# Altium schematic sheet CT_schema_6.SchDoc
size 226 x 144 mm
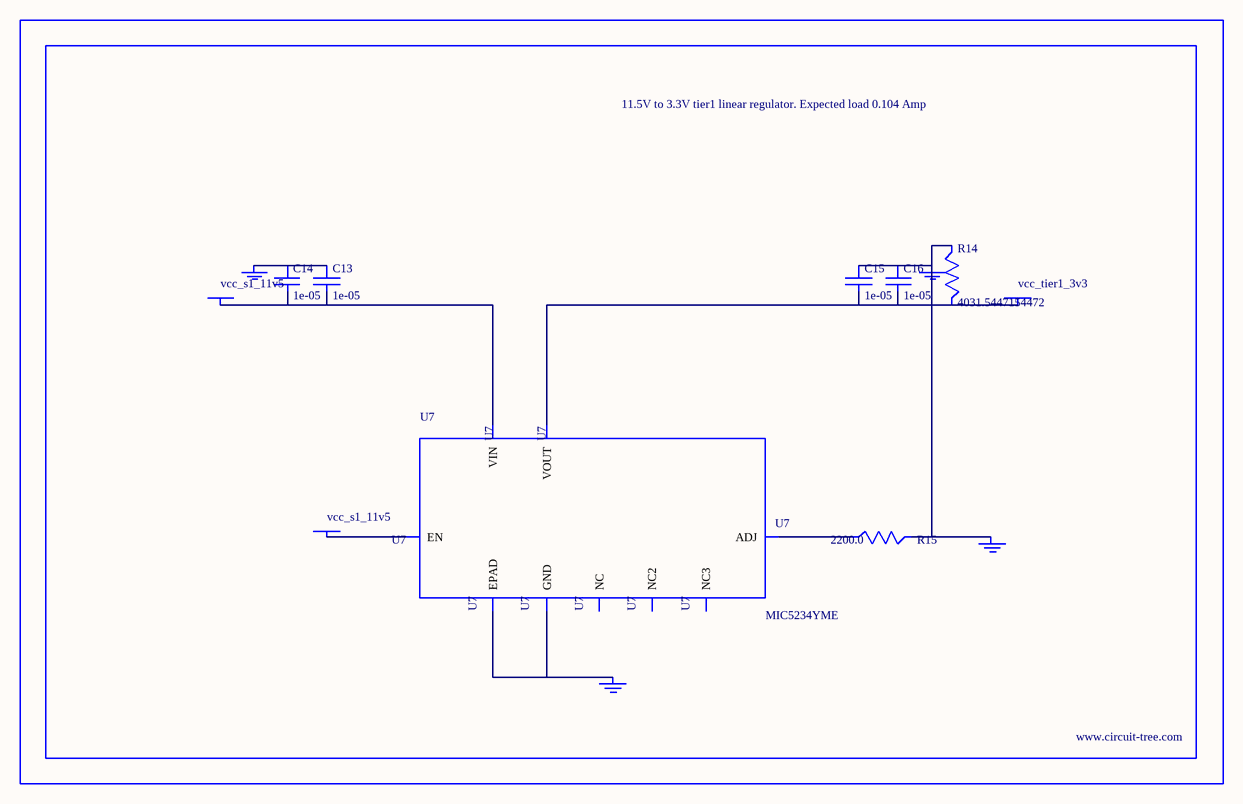
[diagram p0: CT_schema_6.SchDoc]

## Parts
BORDER5  (no value)
C13  1e-05  [C1210]
C14  1e-05  [C1210]
C15  1e-05  [C1210]
C16  1e-05  [C1210]
GND_INSTANCE_5_0  (no value)
GND_INSTANCE_5_1  (no value)
GND_INSTANCE_5_2  (no value)
GND_INSTANCE_5_3  (no value)
POWER_INSTANCE_5_0  vcc_tier1_3v3
POWER_INSTANCE_5_1  vcc_s1_11v5
POWER_INSTANCE_5_2  vcc_s1_11v5
R14  4031.5447154472  [R0603]
R15  2200.0  [R0603]
U7  MIC5234YME  [SOIC-8_EP]

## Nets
NetC13_1: C13.1 C14.1 GND_INSTANCE_5_3.0(GND)
NetC13_2: C13.2 C14.2 POWER_INSTANCE_5_2.0(PWR) U7.8(VIN)
NetC15_1: C15.1 C16.1 GND_INSTANCE_5_0.0(GND) GND_INSTANCE_5_1.0(GND) R14.1 R15.2
NetC15_2: C15.2 C16.2 POWER_INSTANCE_5_0.0(PWR) R14.2 U7.1(VOUT)
NetGND_INSTANCE_5_2_0: GND_INSTANCE_5_2.0(GND) U7.7(GND) U7.EPAD
NetPOWER_INSTANCE_5_1_0: POWER_INSTANCE_5_1.0(PWR) U7.5(EN)
NetR15_1: R15.1 U7.4(ADJ)

Not connected (* = marked no-connect by the designer): U7 2(NC) 3(NC2) 6(NC3)

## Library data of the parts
BORDER5 = BORDER_PAGE5
C13-C16 = C1210C106K5PACTU
GND_INSTANCE_5_0-GND_INSTANCE_5_3 = GND
POWER_INSTANCE_5_0-POWER_INSTANCE_5_2 = PWR
R14 = R14
R15 = RC0603JR-072K2L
